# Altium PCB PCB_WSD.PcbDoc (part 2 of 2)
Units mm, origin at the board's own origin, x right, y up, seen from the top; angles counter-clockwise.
Board outline 55.63 x 89.28 mm, 2 copper layers (Top Layer, Bottom Layer); 49 components, 56 nets, 208 pads, 22 vias.
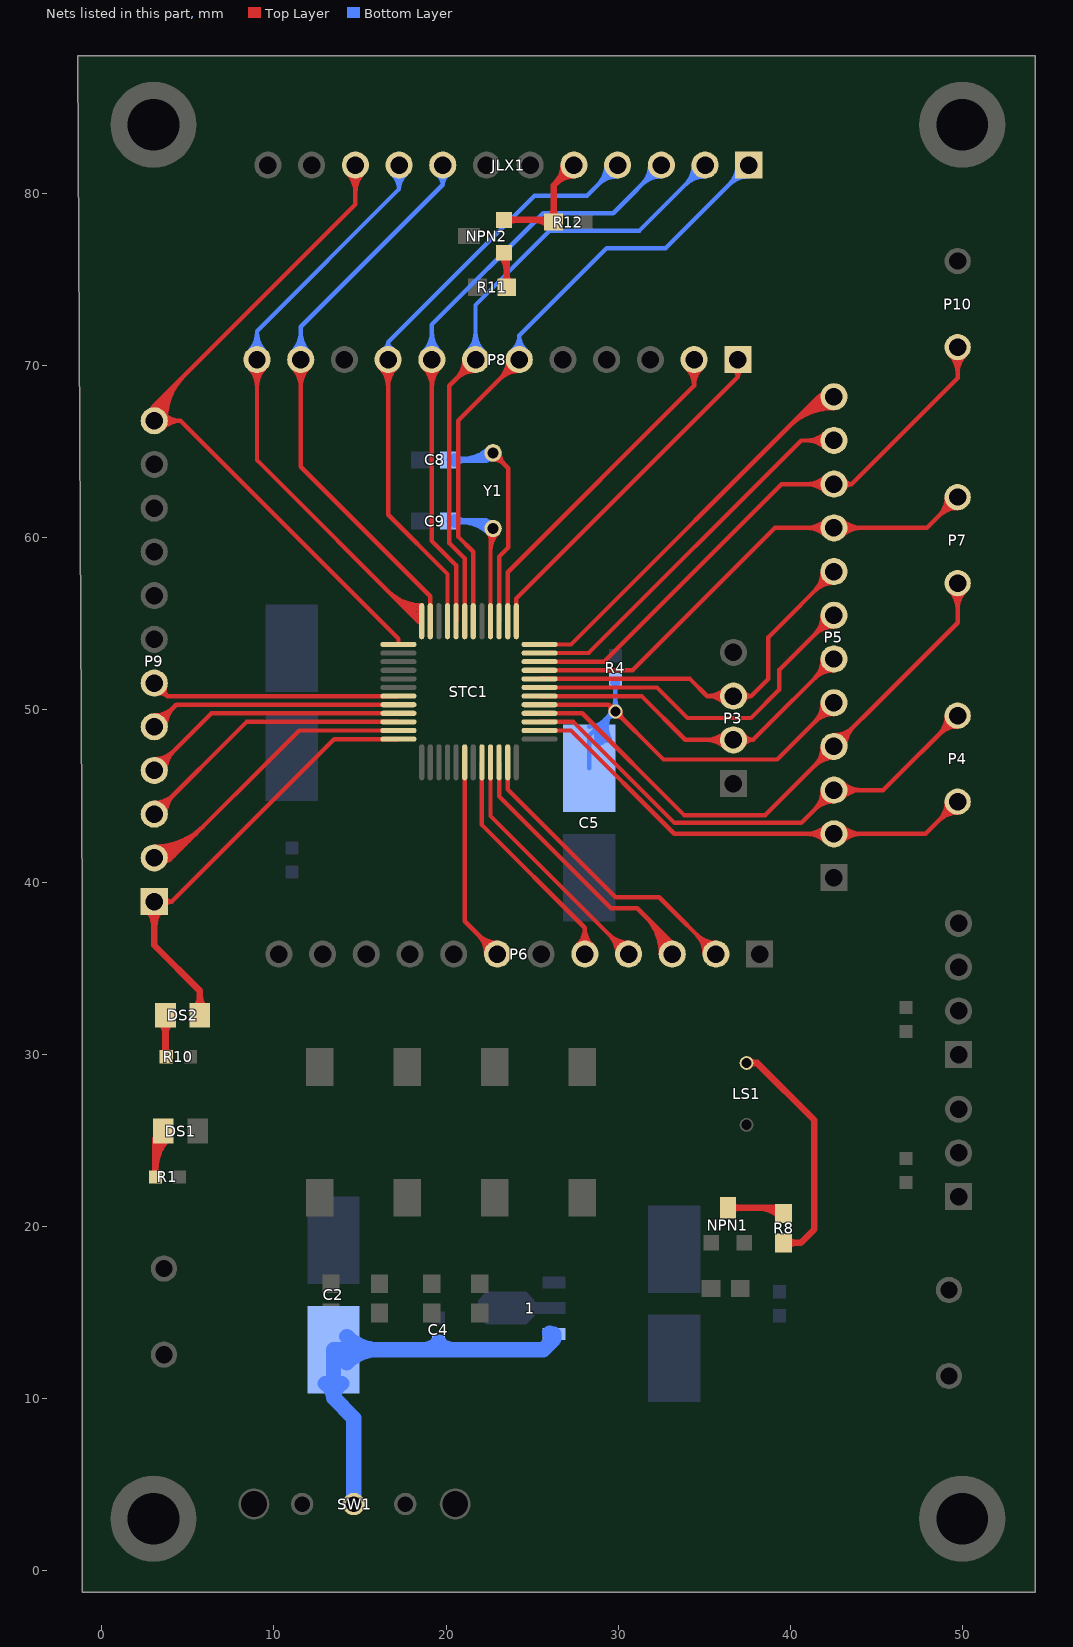
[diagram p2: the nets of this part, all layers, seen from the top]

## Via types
v1: diameter 1.2, hole 1, Top Layer to Bottom Layer, 21 vias
v2: diameter 0.8, hole 0.6, Top Layer to Bottom Layer, 1 vias

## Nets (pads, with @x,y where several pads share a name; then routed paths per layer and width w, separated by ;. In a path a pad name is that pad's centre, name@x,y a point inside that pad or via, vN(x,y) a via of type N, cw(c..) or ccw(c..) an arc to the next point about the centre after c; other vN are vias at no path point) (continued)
LCD-RS: JLX1.10 P9.12 STC1.25 | length 76.2
  Top Layer w0.254: JLX1.10@14.732,81.661 14.732,79.375 3.048,67.691 ; STC1.25@17.236,53.804 17.236,54.138 4.572,66.802 ; 3.048,67.691 cw(c2.78,67.691) 2.857,67.434 ccw(c2.78,67.691) 3.048,67.691 ; 3.048,67.691 ccw(c3.316,67.691) 3.239,67.434 cw(c3.316,67.691) 3.048,67.691 ; 3.048,67.691 P9.12@3.048,66.802 4.572,66.802 ; 3.986,66.802 cw(c3.986,67.681) 3.345,67.08 ccw(c3.986,67.681) 3.986,66.802 ; 3.986,66.802 ccw(c3.986,65.923) 3.345,66.524 cw(c3.986,65.923) 3.986,66.802 ; 4.572,66.802 cw(c4.572,68.23) 3.53,67.254 ccw(c4.572,68.23) 4.572,66.802 ; 4.572,66.802 ccw(c4.572,65.374) 3.53,66.35 cw(c4.572,65.374) 4.572,66.802 ; 14.732,80.067 cw(c16.326,80.067) 15.199,81.194 ccw(c16.326,80.067) 14.732,80.067 ; 14.732,80.067 ccw(c13.138,80.067) 14.265,81.194 cw(c13.138,80.067) 14.732,80.067 ; 14.732,80.68 cw(c15.713,80.68) 15.019,81.374 ccw(c15.713,80.68) 14.732,80.68 ; 14.732,80.68 ccw(c13.751,80.68) 14.445,81.374 cw(c13.751,80.68) 14.732,80.68 ; P9.12@2.692,66.802 cw(c3.98,66.802) 3.07,67.713 ccw(c3.98,66.802) P9.12@2.692,66.802 ; P9.12@2.946,66.802 cw(c4.847,66.802) 3.503,68.146 ccw(c4.847,66.802) P9.12@2.946,66.802 ; P9.12@3.2,66.802 cw(c5.715,66.802) 3.937,68.58 ccw(c5.715,66.802) P9.12@3.2,66.802 ; P9.12@3.454,66.802 cw(c6.582,66.802) 4.37,69.013 ccw(c6.582,66.802) P9.12@3.454,66.802 ; P9.12@3.708,66.802 cw(c7.449,66.802) 4.804,69.447 ccw(c7.449,66.802) P9.12@3.708,66.802
LCD-SCLK: JLX1.8 P8.11 STC1.23 | length 52
  Top Layer w0.254: P8.11@11.557,70.358 11.557,64.135 19.086,56.606 STC1.23@19.086,55.154 ; 11.557,68.764 cw(c13.151,68.764) 12.024,69.891 ccw(c13.151,68.764) 11.557,68.764 ; 11.557,68.764 ccw(c9.963,68.764) 11.09,69.891 cw(c9.963,68.764) 11.557,68.764 ; 11.557,69.377 cw(c12.538,69.377) 11.844,70.071 ccw(c12.538,69.377) 11.557,69.377 ; 11.557,69.377 ccw(c10.576,69.377) 11.27,70.071 cw(c10.576,69.377) 11.557,69.377
  Bottom Layer w0.254: P8.11@11.557,70.358 11.557,72.263 19.812,80.518 ; JLX1.8@19.812,81.661 19.812,80.518 ; 11.557,71.339 cw(c10.576,71.339) 11.27,70.645 ccw(c10.576,71.339) 11.557,71.339 ; 11.557,71.339 ccw(c12.538,71.339) 11.844,70.645 cw(c12.538,71.339) 11.557,71.339 ; 11.557,71.952 cw(c9.963,71.952) 11.09,70.825 ccw(c9.963,71.952) 11.557,71.952 ; 11.557,71.952 ccw(c13.151,71.952) 12.024,70.825 cw(c13.151,71.952) 11.557,71.952 ; 19.812,80.518 cw(c20.471,80.518) 20.142,81.089 ccw(c20.471,80.518) 19.812,80.518 ; 19.812,80.518 ccw(c19.153,80.518) 19.482,81.089 cw(c19.153,80.518) 19.812,80.518
LCD-SDA: JLX1.9 P8.12 STC1.24 | length 68.5
  Top Layer w0.254: P8.12@9.017,70.358 9.017,64.516 18.379,55.154 STC1.24@18.586,55.154 ; 9.017,68.764 cw(c10.611,68.764) 9.484,69.891 ccw(c10.611,68.764) 9.017,68.764 ; 9.017,68.764 ccw(c7.423,68.764) 8.55,69.891 cw(c7.423,68.764) 9.017,68.764 ; 9.017,69.377 cw(c9.998,69.377) 9.304,70.071 ccw(c9.998,69.377) 9.017,69.377 ; 9.017,69.377 ccw(c8.036,69.377) 8.73,70.071 cw(c8.036,69.377) 9.017,69.377 ; 16.657,56.876 ccw(c18.586,58.805) 18.586,56.077 cw(c18.586,58.805) 16.657,56.876 ; 17.091,56.442 ccw(c18.586,57.938) 18.586,55.823 cw(c18.586,57.938) 17.091,56.442 ; 17.524,56.009 ccw(c18.586,57.071) 18.586,55.569 cw(c18.586,57.071) 17.524,56.009 ; 17.958,55.575 ccw(c18.586,56.203) 18.586,55.315 cw(c18.586,56.203) 17.958,55.575 ; 18.391,55.142 ccw(c18.586,55.336) 18.586,55.061 cw(c18.586,55.336) 18.391,55.142
  Bottom Layer w0.254: P8.12@9.017,70.358 9.017,72.009 17.272,80.264 ; JLX1.9@17.272,81.661 17.272,80.264 ; 9.017,71.339 cw(c8.036,71.339) 8.73,70.645 ccw(c8.036,71.339) 9.017,71.339 ; 9.017,71.339 ccw(c9.998,71.339) 9.304,70.645 cw(c9.998,71.339) 9.017,71.339 ; 9.017,71.952 cw(c7.423,71.952) 8.55,70.825 ccw(c7.423,71.952) 9.017,71.952 ; 9.017,71.952 ccw(c10.611,71.952) 9.484,70.825 cw(c10.611,71.952) 9.017,71.952 ; 17.272,80.264 cw(c18.419,80.264) 17.691,81.151 ccw(c18.419,80.264) 17.272,80.264 ; 17.272,80.264 ccw(c16.125,80.264) 16.853,81.151 cw(c16.125,80.264) 17.272,80.264 ; 17.272,80.801 cw(c17.978,80.801) 17.53,81.347 ccw(c17.978,80.801) 17.272,80.801 ; 17.272,80.801 ccw(c16.566,80.801) 17.014,81.347 cw(c16.566,80.801) 17.272,80.801
LED: DS2.2 P9.1 STC1.36 | length 35.5
  Top Layer w0.254: P9.1@3.048,38.862 4.064,38.862 ; STC1.36@17.236,48.304 13.506,48.304 4.064,38.862 ; 4.064,38.862 cw(c4.064,39.313) 3.652,39.13 ccw(c4.064,39.313) 4.064,38.862 ; 4.064,38.862 ccw(c4.064,38.411) 3.652,38.594 cw(c4.064,38.411) 4.064,38.862
  Top Layer w0.381: P9.1@3.048,38.862 3.048,36.322 5.699,33.671 DS2.2@5.699,32.258 ; 3.048,37.421 cw(c4.489,37.421) 3.47,38.44 ccw(c4.489,37.421) 3.048,37.421 ; 3.048,37.421 ccw(c1.607,37.421) 2.626,38.44 cw(c1.607,37.421) 3.048,37.421 ; 5.699,33.372 cw(c4.71,33.372) 5.409,32.673 ccw(c4.71,33.372) 5.699,33.372 ; 5.699,33.372 ccw(c6.688,33.372) 5.989,32.673 cw(c6.688,33.372) 5.699,33.372
Net1_3: 1.3 C2.1 C4.2 SW1.2 | length 45.2
  Bottom Layer w0.889: SW1.2@14.636,3.854 14.636,8.859 13.462,10.033 ; 19.558,12.827 C4.2@19.558,13.271 ; 1.3@26.28,13.74 26.28,13.453 25.654,12.827 C2.1@13.462,12.827 13.462,10.033 ; C2.1@12.964,10.853 cw(c12.538,10.033) 13.462,10.033 ; C2.1@12.964,10.853 cw(c12.538,10.033) 13.462,10.033 ; C2.1@12.964,10.853 cw(c12.538,10.033) 13.462,10.033 ; C2.1@12.964,10.853 cw(c12.538,10.033) 13.462,10.033 ; 13.462,10.033 cw(c14.386,10.033) C2.1@13.96,10.853 ; 13.462,10.033 cw(c14.386,10.033) C2.1@13.96,10.853 ; 13.462,10.033 cw(c14.386,10.033) C2.1@13.96,10.853 ; 13.462,10.033 cw(c14.386,10.033) C2.1@13.96,10.853 ; 16.068,12.827 cw(c16.068,15.433) 14.225,13.59 ccw(c16.068,15.433) 16.068,12.827 ; 16.068,12.827 ccw(c16.068,10.221) 14.225,12.064 cw(c16.068,10.221) 16.068,12.827 ; 18.638,12.827 ccw(c18.638,14.191) 19.603,13.227 cw(c18.638,14.191) 18.638,12.827 ; C4.2@19.513,13.227 ccw(c20.478,14.191) 20.478,12.827 cw(c20.478,14.191) C4.2@19.513,13.227 ; 25.96,13.133 ccw(c25.585,13.508) 26.035,13.79 cw(c25.585,13.508) 25.96,13.133
NetC8_1: C8.1 STC1.15 Y1.1 | length 25.2
  Top Layer w0.254: Y1.1@22.733,64.938 23.622,64.049 23.622,59.436 23.086,58.9 STC1.15@23.086,55.154 ; 23.383,64.288 cw(c24.034,64.938) 23.114,64.938 ccw(c24.034,64.938) 23.383,64.288 ; 23.383,64.288 ccw(c22.733,63.637) 22.733,64.557 cw(c22.733,63.637) 23.383,64.288
  Bottom Layer w0.381: C8.1@20.209,64.527 22.322,64.527 ; Y1.1@22.733,64.938 22.322,64.527 ; 21.006,64.527 cw(c21.006,65.274) 20.478,64.746 ccw(c21.006,65.274) 21.006,64.527 ; 21.006,64.527 ccw(c21.006,63.78) 20.478,64.308 cw(c21.006,63.78) 21.006,64.527 ; 22.322,64.527 cw(c22.586,64.263) 22.665,64.628 ccw(c22.586,64.263) 22.322,64.527 ; 22.322,64.527 ccw(c22.058,64.791) 22.423,64.87 cw(c22.058,64.791) 22.322,64.527 ; 20.974,64.527 ccw(c20.974,66.697) 22.508,65.163 cw(c20.974,66.697) 20.974,64.527 ; 21.894,64.527 ccw(c21.894,65.777) 22.778,64.893 cw(c21.894,65.777) 21.894,64.527
NetC9_1: C9.1 STC1.16 Y1.2 | length 21.9
  Top Layer w0.254: STC1.16@22.586,55.154 22.586,60.391 Y1.2@22.733,60.538 ; Y1.2@22.464,60.269 cw(c22.168,59.973) 22.586,59.973 ccw(c22.168,59.973) Y1.2@22.464,60.269 ; 22.586,59.263 cw(c24.008,59.263) 23.002,60.269 ccw(c24.008,59.263) 22.586,59.263 ; 22.586,59.877 cw(c23.394,59.877) 22.823,60.448 ccw(c23.394,59.877) 22.586,59.877
  Bottom Layer w0.381: C9.1@20.209,60.971 22.3,60.971 ; Y1.2@22.733,60.538 22.3,60.971 ; 21.006,60.971 cw(c21.006,61.718) 20.478,61.19 ccw(c21.006,61.718) 21.006,60.971 ; 21.006,60.971 ccw(c21.006,60.224) 20.478,60.752 cw(c21.006,60.224) 21.006,60.971 ; 22.3,60.971 cw(c21.995,60.666) 22.42,60.592 ccw(c21.995,60.666) 22.3,60.971 ; 22.3,60.971 ccw(c22.605,61.276) 22.679,60.851 cw(c22.605,61.276) 22.3,60.971 ; 20.921,60.971 cw(c20.921,58.726) 22.508,60.313 ccw(c20.921,58.726) 20.921,60.971 ; 21.841,60.971 cw(c21.841,59.646) 22.778,60.583 ccw(c21.841,59.646) 21.841,60.971
NetDS1_1: DS1.1 R1.1 | length 10.9
  Top Layer w0.381: R1.1@3.111,22.86 3.111,25.066 DS1.1@3.572,25.527 ; 3.111,23.32 cw(c2.652,23.32) 2.977,22.995 ccw(c2.652,23.32) 3.111,23.32 ; 3.111,23.32 ccw(c3.571,23.32) 3.246,22.995 cw(c3.571,23.32) 3.111,23.32 ; 3.111,23.302 cw(c5.672,23.302) 3.862,25.112 ccw(c5.672,23.302) 3.111,23.302 ; 3.111,24.221 cw(c4.753,24.221) 3.592,25.382 ccw(c4.753,24.221) 3.111,24.221
NetDS2_1: DS2.1 R10.1 | length 6.5
  Top Layer w0.381: DS2.1@3.699,32.258 3.699,29.892 R10.1@3.746,29.845 ; 3.699,31.144 cw(c4.688,31.144) 3.989,31.843 ccw(c4.688,31.144) 3.699,31.144 ; 3.699,31.144 ccw(c2.71,31.144) 3.409,31.843 cw(c2.71,31.144) 3.699,31.144 ; 3.699,30.42 ccw(c4.321,30.42) 3.881,29.98 cw(c4.321,30.42) 3.699,30.42
NetJLX1_5: JLX1.5 NPN2.2 R12.2 | length 17.5
  Top Layer w0.381: NPN2.2@23.376,78.473 26.131,78.473 R12.2@26.256,78.348 26.256,80.485 JLX1.5@27.432,81.661 ; 24.02,78.473 cw(c24.02,79.117) 23.565,78.662 ccw(c24.02,79.117) 24.02,78.473 ; 24.02,78.473 ccw(c24.02,77.829) 23.565,78.284 cw(c24.02,77.829) 24.02,78.473 ; 26.256,79.095 cw(c25.509,79.095) 26.037,78.567 ccw(c25.509,79.095) 26.256,79.095 ; 26.256,79.095 ccw(c27.003,79.095) 26.475,78.567 cw(c27.003,79.095) 26.256,79.095 ; 26.413,80.642 cw(c27.432,79.623) 27.432,81.064 ccw(c27.432,79.623) 26.413,80.642 ; 26.413,80.642 ccw(c25.394,81.661) 26.835,81.661 cw(c25.394,81.661) 26.413,80.642 ; 25.157,78.473 cw(c25.157,77.299) 25.987,78.129 ccw(c25.157,77.299) 25.157,78.473
NetLS1_2: LS1.2 R8.1 | length 17.7
  Top Layer w0.381: LS1.2@37.465,29.486 38.078,29.486 41.402,26.162 41.402,19.812 40.624,19.034 R8.1@39.613,19.034 ; 37.971,29.486 cw(c37.971,29.992) 37.613,29.634 ccw(c37.971,29.992) 37.971,29.486 ; 37.971,29.486 ccw(c37.971,28.98) 37.613,29.338 cw(c37.971,28.98) 37.971,29.486 ; 40.36,19.034 cw(c40.36,19.781) 39.832,19.253 ccw(c40.36,19.781) 40.36,19.034 ; 40.36,19.034 ccw(c40.36,18.287) 39.832,18.815 cw(c40.36,18.287) 40.36,19.034
NetNPN1_3: NPN1.3 R8.2 | length 9.4
  Top Layer w0.381: NPN1.3@36.385,21.074 39.273,21.074 R8.2@39.613,20.734 ; 37.029,21.074 cw(c37.029,21.718) 36.574,21.263 ccw(c37.029,21.718) 37.029,21.074 ; 37.029,21.074 ccw(c37.029,20.43) 36.574,20.885 cw(c37.029,20.43) 37.029,21.074 ; 38.166,21.074 cw(c38.166,19.337) 39.394,20.565 ccw(c38.166,19.337) 38.166,21.074 ; 39.085,21.074 cw(c39.085,20.256) 39.664,20.835 ccw(c39.085,20.256) 39.085,21.074
NetNPN2_1: NPN2.1 R11.2 | length 6.2
  Top Layer w0.381: NPN2.1@23.376,76.568 23.528,76.416 R11.2@23.528,74.56 ; 23.528,75.307 cw(c22.781,75.307) 23.309,74.779 ccw(c22.781,75.307) 23.528,75.307 ; 23.528,75.307 ccw(c24.275,75.307) 23.747,74.779 cw(c24.275,75.307) 23.528,75.307 ; NPN2.1@23.187,76.379 cw(c22.365,75.557) 23.528,75.557 ccw(c22.365,75.557) NPN2.1@23.187,76.379
P4.0: JLX1.1 P8.6 STC1.18 | length 58.6
  Top Layer w0.254: STC1.18@21.586,55.154 21.586,59.186 20.701,60.071 20.701,66.802 P8.6@24.257,70.358 ; 23.13,69.231 cw(c24.257,68.103) 24.257,69.698 ccw(c24.257,68.103) 23.13,69.231 ; 23.13,69.231 ccw(c22.002,70.358) 23.597,70.358 cw(c22.002,70.358) 23.13,69.231 ; 23.563,69.664 cw(c24.257,68.97) 24.257,69.952 ccw(c24.257,68.97) 23.563,69.664 ; 23.563,69.664 ccw(c22.869,70.358) 23.851,70.358 cw(c22.869,70.358) 23.563,69.664
  Bottom Layer w0.254: P8.6@24.257,70.358 24.257,71.755 ; JLX1.1@37.592,81.661 32.766,76.835 29.337,76.835 24.257,71.755 ; 24.257,71.218 cw(c23.551,71.218) 23.999,70.672 ccw(c23.551,71.218) 24.257,71.218 ; 24.257,71.218 ccw(c24.963,71.218) 24.515,70.672 cw(c24.963,71.218) 24.257,71.218 ; 24.257,71.755 cw(c23.11,71.755) 23.838,70.868 ccw(c23.11,71.755) 24.257,71.755 ; 24.257,71.755 ccw(c25.404,71.755) 24.676,70.868 cw(c25.404,71.755) 24.257,71.755 ; 36.465,80.534 cw(c37.592,79.406) 37.592,81.001 ccw(c37.592,79.406) 36.465,80.534 ; 36.465,80.534 ccw(c35.337,81.661) 36.932,81.661 cw(c35.337,81.661) 36.465,80.534 ; JLX1.1@36.898,80.967 cw(c37.592,80.273) 37.592,81.255 ccw(c37.592,80.273) JLX1.1@36.898,80.967 ; JLX1.1@36.898,80.967 ccw(c36.204,81.661) 37.186,81.661 cw(c36.204,81.661) JLX1.1@36.898,80.967
P05: P9.2 STC1.35 | length 40.9
  Top Layer w0.254: P9.2@3.048,41.402 3.175,41.275 3.937,41.275 ; STC1.35@17.236,48.804 11.466,48.804 3.937,41.275 ; 3.937,41.275 cw(c3.937,41.51) 3.704,41.482 ccw(c3.937,41.51) 3.937,41.275 ; 3.937,41.275 ccw(c3.937,40.928) 3.631,41.091 cw(c3.937,40.928) 3.937,41.275 ; P9.2@3.048,41.046 ccw(c3.048,42.641) 4.175,41.513 cw(c3.048,42.641) P9.2@3.048,41.046 ; P9.2@3.048,41.3 ccw(c3.048,43.508) 4.609,41.947 cw(c3.048,43.508) P9.2@3.048,41.3 ; P9.2@3.048,41.554 ccw(c3.048,44.375) 5.043,42.381 cw(c3.048,44.375) P9.2@3.048,41.554 ; P9.2@3.048,41.808 ccw(c3.048,45.242) 5.476,42.814 cw(c3.048,45.242) P9.2@3.048,41.808 ; P9.2@3.048,42.062 ccw(c3.048,46.11) 5.91,43.248 cw(c3.048,46.11) P9.2@3.048,42.062
P06: P9.3 STC1.34 | length 24.5
  Top Layer w0.254: P9.3@3.048,43.942 8.41,49.304 STC1.34@17.236,49.304 ; 3.742,44.636 cw(c3.048,45.33) 3.048,44.348 ccw(c3.048,45.33) 3.742,44.636 ; 3.742,44.636 ccw(c4.436,43.942) 3.454,43.942 cw(c4.436,43.942) 3.742,44.636 ; 4.175,45.069 cw(c3.048,46.197) 3.048,44.602 ccw(c3.048,46.197) 4.175,45.069 ; 4.175,45.069 ccw(c5.303,43.942) 3.708,43.942 cw(c5.303,43.942) 4.175,45.069
P07: P9.4 STC1.33 | length 23.7
  Top Layer w0.254: P9.4@3.048,46.482 6.37,49.804 STC1.33@17.236,49.804 ; 3.742,47.176 cw(c3.048,47.87) 3.048,46.888 ccw(c3.048,47.87) 3.742,47.176 ; 3.742,47.176 ccw(c4.436,46.482) 3.454,46.482 cw(c4.436,46.482) 3.742,47.176 ; 4.175,47.609 cw(c3.048,48.737) 3.048,47.142 ccw(c3.048,48.737) 4.175,47.609 ; 4.175,47.609 ccw(c5.303,46.482) 3.708,46.482 cw(c5.303,46.482) 4.175,47.609
P11: P6.5 STC1.44 | length 21.2
  Top Layer w0.254: STC1.44@22.086,46.954 22.086,43.319 28.067,37.338 ; P6.5@28.067,35.814 28.067,37.338 ; 28.067,36.752 cw(c27.188,36.752) 27.789,36.111 ccw(c27.188,36.752) 28.067,36.752 ; 28.067,36.752 ccw(c28.946,36.752) 28.345,36.111 cw(c28.946,36.752) 28.067,36.752 ; 28.067,37.338 cw(c26.639,37.338) 27.615,36.296 ccw(c26.639,37.338) 28.067,37.338 ; 28.067,37.338 ccw(c29.495,37.338) 28.519,36.296 cw(c29.495,37.338) 28.067,37.338
P12: P6.4 STC1.45 | length 22.6
  Top Layer w0.254: STC1.45@22.586,46.954 22.586,43.835 P6.4@30.607,35.814 ; 29.48,36.941 cw(c28.352,35.814) 29.947,35.814 ccw(c28.352,35.814) 29.48,36.941 ; 29.48,36.941 ccw(c30.607,38.069) 30.607,36.474 cw(c30.607,38.069) 29.48,36.941 ; 29.913,36.508 cw(c29.219,35.814) 30.201,35.814 ccw(c29.219,35.814) 29.913,36.508 ; 29.913,36.508 ccw(c30.607,37.202) 30.607,36.22 cw(c30.607,37.202) 29.913,36.508
P13: P6.3 STC1.46 | length 30.1
  Top Layer w0.254: STC1.46@23.086,46.954 23.086,44.986 29.591,38.481 31.115,38.481 33.147,36.449 P6.3@33.147,35.814 ; 31.571,38.025 cw(c29.359,35.814) 32.487,35.814 ccw(c29.359,35.814) 31.571,38.025 ; 32.004,37.592 cw(c30.226,35.814) 32.741,35.814 ccw(c30.226,35.814) 32.004,37.592 ; 32.438,37.158 cw(c31.094,35.814) 32.995,35.814 ccw(c31.094,35.814) 32.438,37.158 ; 32.871,36.725 cw(c31.961,35.814) 33.249,35.814 ccw(c31.961,35.814) 32.871,36.725
P14: P6.2 STC1.47 | length 25.7
  Top Layer w0.254: STC1.47@23.586,46.954 23.586,45.375 29.845,39.116 32.385,39.116 P6.2@35.687,35.814 ; 34.56,36.941 cw(c33.432,35.814) 35.027,35.814 ccw(c33.432,35.814) 34.56,36.941 ; 34.56,36.941 ccw(c35.687,38.069) 35.687,36.474 cw(c35.687,38.069) 34.56,36.941 ; 34.993,36.508 cw(c34.299,35.814) 35.281,35.814 ccw(c34.299,35.814) 34.993,36.508 ; 34.993,36.508 ccw(c35.687,37.202) 35.687,36.22 cw(c35.687,37.202) 34.993,36.508
P15: P4.1 P5.2 STC1.2 | length 51.4
  Top Layer w0.254: STC1.2@25.436,48.804 27.262,48.804 33.267,42.799 47.867,42.799 P4.1@49.732,44.664 ; 40.951,42.799 cw(c40.951,41.205) 42.078,42.332 ccw(c40.951,41.205) 40.951,42.799 ; 40.951,42.799 ccw(c40.951,44.393) 42.078,43.266 cw(c40.951,44.393) 40.951,42.799 ; 41.564,42.799 cw(c41.564,41.818) 42.258,42.512 ccw(c41.564,41.818) 41.564,42.799 ; 41.564,42.799 ccw(c41.564,43.78) 42.258,43.086 cw(c41.564,43.78) 41.564,42.799 ; 43.526,42.799 cw(c43.526,43.78) 42.832,43.086 ccw(c43.526,43.78) 43.526,42.799 ; 43.526,42.799 ccw(c43.526,41.818) 42.832,42.512 cw(c43.526,41.818) 43.526,42.799 ; 44.139,42.799 cw(c44.139,44.393) 43.012,43.266 ccw(c44.139,44.393) 44.139,42.799 ; 44.139,42.799 ccw(c44.139,41.205) 43.012,42.332 cw(c44.139,41.205) 44.139,42.799 ; 48.648,43.58 cw(c49.732,42.496) 49.732,44.029 ccw(c49.732,42.496) 48.648,43.58 ; 48.648,43.58 ccw(c47.564,44.664) 49.097,44.664 cw(c47.564,44.664) 48.648,43.58 ; 49.082,44.014 cw(c49.732,43.363) 49.732,44.283 ccw(c49.732,43.363) 49.082,44.014 ; 49.082,44.014 ccw(c48.431,44.664) 49.351,44.664 cw(c48.431,44.664) 49.082,44.014
P16: P4.2 P5.3 STC1.3 | length 53.2
  Top Layer w0.254: STC1.3@25.436,49.304 27.404,49.304 33.274,43.434 40.64,43.434 P5.3@42.545,45.339 45.407,45.339 P4.2@49.732,49.664 ; 41.418,44.212 cw(c42.545,43.084) 42.545,44.679 ccw(c42.545,43.084) 41.418,44.212 ; 41.418,44.212 ccw(c40.29,45.339) 41.885,45.339 cw(c40.29,45.339) 41.418,44.212 ; 41.851,44.645 cw(c42.545,43.951) 42.545,44.933 ccw(c42.545,43.951) 41.851,44.645 ; 41.851,44.645 ccw(c41.157,45.339) 42.139,45.339 cw(c41.157,45.339) 41.851,44.645 ; 43.526,45.339 cw(c43.526,46.32) 42.832,45.626 ccw(c43.526,46.32) 43.526,45.339 ; 43.526,45.339 ccw(c43.526,44.358) 42.832,45.052 cw(c43.526,44.358) 43.526,45.339 ; 44.139,45.339 cw(c44.139,46.933) 43.012,45.806 ccw(c44.139,46.933) 44.139,45.339 ; 44.139,45.339 ccw(c44.139,43.745) 43.012,44.872 cw(c44.139,43.745) 44.139,45.339 ; 48.648,48.58 cw(c49.732,47.496) 49.732,49.029 ccw(c49.732,47.496) 48.648,48.58 ; 48.648,48.58 ccw(c47.564,49.664) 49.097,49.664 cw(c47.564,49.664) 48.648,48.58 ; 49.082,49.014 cw(c49.732,48.363) 49.732,49.283 ccw(c49.732,48.363) 49.082,49.014 ; 49.082,49.014 ccw(c48.431,49.664) 49.351,49.664 cw(c48.431,49.664) 49.082,49.014
P17: P5.4 P7.1 STC1.4 | length 57.6
  Top Layer w0.254: STC1.4@25.436,49.804 27.92,49.804 33.836,43.888 38.554,43.888 49.732,55.066 P7.1@49.732,57.364 ; 41.418,46.752 cw(c42.545,45.624) 42.545,47.219 ccw(c42.545,45.624) 41.418,46.752 ; 41.418,46.752 ccw(c40.29,47.879) 41.885,47.879 cw(c40.29,47.879) 41.418,46.752 ; 41.851,47.185 cw(c42.545,46.491) 42.545,47.473 ccw(c42.545,46.491) 41.851,47.185 ; 41.851,47.185 ccw(c41.157,47.879) 42.139,47.879 cw(c41.157,47.879) 41.851,47.185 ; 43.239,48.573 cw(c42.545,49.267) 42.545,48.285 ccw(c42.545,49.267) 43.239,48.573 ; 43.239,48.573 ccw(c43.933,47.879) 42.951,47.879 cw(c43.933,47.879) 43.239,48.573 ; 43.672,49.006 cw(c42.545,50.134) 42.545,48.539 ccw(c42.545,50.134) 43.672,49.006 ; 43.672,49.006 ccw(c44.8,47.879) 43.205,47.879 cw(c44.8,47.879) 43.672,49.006 ; 49.732,55.831 cw(c51.265,55.831) 50.181,56.915 ccw(c51.265,55.831) 49.732,55.831 ; 49.732,55.831 ccw(c48.199,55.831) 49.283,56.915 cw(c48.199,55.831) 49.732,55.831 ; 49.732,56.444 cw(c50.652,56.444) 50.001,57.095 ccw(c50.652,56.444) 49.732,56.444 ; 49.732,56.444 ccw(c48.812,56.444) 49.463,57.095 cw(c48.812,56.444) 49.732,56.444
P20: JLX1.2 P8.7 STC1.19 | length 60.4
  Top Layer w0.254: STC1.19@21.086,55.154 21.086,58.801 20.193,59.694 20.193,68.834 P8.7@21.717,70.358 ; 20.59,69.231 cw(c21.717,68.103) 21.717,69.698 ccw(c21.717,68.103) 20.59,69.231 ; 20.59,69.231 ccw(c19.462,70.358) 21.057,70.358 cw(c19.462,70.358) 20.59,69.231 ; 21.023,69.664 cw(c21.717,68.97) 21.717,69.952 ccw(c21.717,68.97) 21.023,69.664 ; 21.023,69.664 ccw(c20.329,70.358) 21.311,70.358 cw(c20.329,70.358) 21.023,69.664
  Bottom Layer w0.254: P8.7@21.717,70.358 21.717,73.533 26.035,77.851 31.242,77.851 JLX1.2@35.052,81.661 ; 21.717,71.339 cw(c20.736,71.339) 21.43,70.645 ccw(c20.736,71.339) 21.717,71.339 ; 21.717,71.339 ccw(c22.698,71.339) 22.004,70.645 cw(c22.698,71.339) 21.717,71.339 ; 21.717,71.952 cw(c20.123,71.952) 21.25,70.825 ccw(c20.123,71.952) 21.717,71.952 ; 21.717,71.952 ccw(c23.311,71.952) 22.184,70.825 cw(c23.311,71.952) 21.717,71.952 ; 33.925,80.534 cw(c35.052,79.406) 35.052,81.001 ccw(c35.052,79.406) 33.925,80.534 ; 33.925,80.534 ccw(c32.797,81.661) 34.392,81.661 cw(c32.797,81.661) 33.925,80.534 ; 34.358,80.967 cw(c35.052,80.273) 35.052,81.255 ccw(c35.052,80.273) 34.358,80.967 ; 34.358,80.967 ccw(c33.664,81.661) 34.646,81.661 cw(c33.664,81.661) 34.358,80.967
P21: JLX1.3 P8.8 STC1.20 | length 59.3
  Top Layer w0.254: P8.8@19.177,70.358 19.177,59.817 20.586,58.408 STC1.20@20.586,55.154 ; 19.177,68.764 cw(c20.771,68.764) 19.644,69.891 ccw(c20.771,68.764) 19.177,68.764 ; 19.177,68.764 ccw(c17.583,68.764) 18.71,69.891 cw(c17.583,68.764) 19.177,68.764 ; 19.177,69.377 cw(c20.158,69.377) 19.464,70.071 ccw(c20.158,69.377) 19.177,69.377 ; 19.177,69.377 ccw(c18.196,69.377) 18.89,70.071 cw(c18.196,69.377) 19.177,69.377
  Bottom Layer w0.254: P8.8@19.177,70.358 19.177,72.39 25.654,78.867 29.718,78.867 JLX1.3@32.512,81.661 ; 19.177,71.339 cw(c18.196,71.339) 18.89,70.645 ccw(c18.196,71.339) 19.177,71.339 ; 19.177,71.339 ccw(c20.158,71.339) 19.464,70.645 cw(c20.158,71.339) 19.177,71.339 ; 19.177,71.952 cw(c17.583,71.952) 18.71,70.825 ccw(c17.583,71.952) 19.177,71.952 ; 19.177,71.952 ccw(c20.771,71.952) 19.644,70.825 cw(c20.771,71.952) 19.177,71.952 ; 31.385,80.534 cw(c32.512,79.406) 32.512,81.001 ccw(c32.512,79.406) 31.385,80.534 ; 31.385,80.534 ccw(c30.257,81.661) 31.852,81.661 cw(c30.257,81.661) 31.385,80.534 ; 31.818,80.967 cw(c32.512,80.273) 32.512,81.255 ccw(c32.512,80.273) 31.818,80.967 ; 31.818,80.967 ccw(c31.124,81.661) 32.106,81.661 cw(c31.124,81.661) 31.818,80.967
P22: JLX1.4 P8.9 STC1.21 | length 53.5
  Top Layer w0.254: P8.9@16.637,70.358 16.637,61.341 20.086,57.892 STC1.21@20.086,55.154 ; 16.637,68.764 cw(c18.231,68.764) 17.104,69.891 ccw(c18.231,68.764) 16.637,68.764 ; 16.637,68.764 ccw(c15.043,68.764) 16.17,69.891 cw(c15.043,68.764) 16.637,68.764 ; 16.637,69.377 cw(c17.618,69.377) 16.924,70.071 ccw(c17.618,69.377) 16.637,69.377 ; 16.637,69.377 ccw(c15.656,69.377) 16.35,70.071 cw(c15.656,69.377) 16.637,69.377
  Bottom Layer w0.254: P8.9@16.637,70.358 16.637,71.374 ; JLX1.4@29.972,81.661 28.194,79.883 25.146,79.883 16.637,71.374 ; 16.637,71.374 cw(c16.186,71.374) 16.369,70.962 ccw(c16.186,71.374) 16.637,71.374 ; 16.637,71.374 ccw(c17.088,71.374) 16.905,70.962 cw(c17.088,71.374) 16.637,71.374 ; 28.845,80.534 cw(c29.972,79.406) 29.972,81.001 ccw(c29.972,79.406) 28.845,80.534 ; 28.845,80.534 ccw(c27.717,81.661) 29.312,81.661 cw(c27.717,81.661) 28.845,80.534 ; 29.278,80.967 cw(c29.972,80.273) 29.972,81.255 ccw(c29.972,80.273) 29.278,80.967 ; 29.278,80.967 ccw(c28.584,81.661) 29.566,81.661 cw(c28.584,81.661) 29.278,80.967
P30: P3.2 P5.6 STC1.6 | length 39.1
  Top Layer w0.254: STC1.6@25.436,50.804 31.365,50.804 33.909,48.26 37.846,48.26 ; P5.6@42.545,52.959 37.846,48.26 ; 35.109,48.26 cw(c35.109,46.666) 36.236,47.793 ccw(c35.109,46.666) 35.109,48.26 ; 35.109,48.26 ccw(c35.109,49.854) 36.236,48.727 cw(c35.109,49.854) 35.109,48.26 ; 35.722,48.26 cw(c35.722,47.279) 36.416,47.973 ccw(c35.722,47.279) 35.722,48.26 ; 35.722,48.26 ccw(c35.722,49.241) 36.416,48.547 cw(c35.722,49.241) 35.722,48.26 ; 37.846,48.26 cw(c37.846,48.919) 37.275,48.59 ccw(c37.846,48.919) 37.846,48.26 ; 37.846,48.26 ccw(c37.846,47.601) 37.275,47.93 cw(c37.846,47.601) 37.846,48.26 ; 41.418,51.832 cw(c42.545,50.704) 42.545,52.299 ccw(c42.545,50.704) 41.418,51.832 ; 41.418,51.832 ccw(c40.29,52.959) 41.885,52.959 cw(c40.29,52.959) 41.418,51.832 ; 41.851,52.265 cw(c42.545,51.571) 42.545,52.553 ccw(c42.545,51.571) 41.851,52.265 ; 41.851,52.265 ccw(c41.157,52.959) 42.139,52.959 cw(c41.157,52.959) 41.851,52.265
P31: P3.3 P5.8 STC1.8 | length 39.7
  Top Layer w0.254: STC1.8@25.436,51.804 34.175,51.804 35.179,50.8 ; P5.8@42.545,58.039 38.735,54.229 38.735,51.816 37.719,50.8 ; 35.179,50.8 cw(c35.179,49.372) 36.221,50.348 ccw(c35.179,49.372) 35.179,50.8 ; 35.179,50.8 ccw(c35.179,52.228) 36.221,51.252 cw(c35.179,52.228) 35.179,50.8 ; 35.179,50.8 37.719,50.8 ; 35.765,50.8 cw(c35.765,49.921) 36.406,50.522 ccw(c35.765,49.921) 35.765,50.8 ; 35.765,50.8 ccw(c35.765,51.679) 36.406,51.078 cw(c35.765,51.679) 35.765,50.8 ; 37.719,50.8 cw(c37.719,51.251) 37.307,51.068 ccw(c37.719,51.251) 37.719,50.8 ; 37.719,50.8 ccw(c37.719,50.349) 37.307,50.532 cw(c37.719,50.349) 37.719,50.8 ; 41.418,56.912 cw(c42.545,55.784) 42.545,57.379 ccw(c42.545,55.784) 41.418,56.912 ; 41.418,56.912 ccw(c40.29,58.039) 41.885,58.039 cw(c40.29,58.039) 41.418,56.912 ; 41.851,57.345 cw(c42.545,56.651) 42.545,57.633 ccw(c42.545,56.651) 41.851,57.345 ; 41.851,57.345 ccw(c41.157,58.039) 42.139,58.039 cw(c41.157,58.039) 41.851,57.345
P32: P5.9 P7.2 STC1.9 | length 52.4
  Top Layer w0.254: STC1.9@25.436,52.304 30.841,52.304 39.116,60.579 47.947,60.579 P7.2@49.732,62.364 ; 40.951,60.579 cw(c40.951,58.985) 42.078,60.112 ccw(c40.951,58.985) 40.951,60.579 ; 40.951,60.579 ccw(c40.951,62.173) 42.078,61.046 cw(c40.951,62.173) 40.951,60.579 ; 41.564,60.579 cw(c41.564,59.598) 42.258,60.292 ccw(c41.564,59.598) 41.564,60.579 ; 41.564,60.579 ccw(c41.564,61.56) 42.258,60.866 cw(c41.564,61.56) 41.564,60.579 ; 43.526,60.579 cw(c43.526,61.56) 42.832,60.866 ccw(c43.526,61.56) 43.526,60.579 ; 43.526,60.579 ccw(c43.526,59.598) 42.832,60.292 cw(c43.526,59.598) 43.526,60.579 ; 44.139,60.579 cw(c44.139,62.173) 43.012,61.046 ccw(c44.139,62.173) 44.139,60.579 ; 44.139,60.579 ccw(c44.139,58.985) 43.012,60.112 cw(c44.139,58.985) 44.139,60.579 ; 48.648,61.28 cw(c49.732,60.196) 49.732,61.729 ccw(c49.732,60.196) 48.648,61.28 ; 48.648,61.28 ccw(c47.564,62.364) 49.097,62.364 cw(c47.564,62.364) 48.648,61.28 ; 49.082,61.714 cw(c49.732,61.063) 49.732,61.983 ccw(c49.732,61.063) 49.082,61.714 ; 49.082,61.714 ccw(c48.431,62.364) 49.351,62.364 cw(c48.431,62.364) 49.082,61.714
P33: P5.10 P10.1 STC1.10 | length 50.8
  Top Layer w0.254: STC1.10@25.436,52.804 29.182,52.804 39.497,63.119 43.561,63.119 ; P10.1@49.732,71.08 49.732,69.29 43.561,63.119 ; 40.951,63.119 cw(c40.951,61.525) 42.078,62.652 ccw(c40.951,61.525) 40.951,63.119 ; 40.951,63.119 ccw(c40.951,64.713) 42.078,63.586 cw(c40.951,64.713) 40.951,63.119 ; 41.564,63.119 cw(c41.564,62.138) 42.258,62.832 ccw(c41.564,62.138) 41.564,63.119 ; 41.564,63.119 ccw(c41.564,64.1) 42.258,63.406 cw(c41.564,64.1) 41.564,63.119 ; 43.561,63.119 cw(c43.561,63.57) 43.149,63.387 ccw(c43.561,63.57) 43.561,63.119 ; 43.561,63.119 ccw(c43.561,62.668) 43.149,62.851 cw(c43.561,62.668) 43.561,63.119 ; 49.732,69.547 cw(c51.265,69.547) 50.181,70.631 ccw(c51.265,69.547) 49.732,69.547 ; 49.732,69.547 ccw(c48.199,69.547) 49.283,70.631 cw(c48.199,69.547) 49.732,69.547 ; 49.732,70.16 cw(c50.652,70.16) 50.001,70.811 ccw(c50.652,70.16) 49.732,70.16 ; 49.732,70.16 ccw(c48.812,70.16) 49.463,70.811 cw(c48.812,70.16) 49.732,70.16
P34: P5.11 STC1.11 | length 30.3
  Top Layer w0.254: STC1.11@25.436,53.304 28.285,53.304 40.64,65.659 P5.11@42.545,65.659 ; 40.951,65.659 cw(c40.951,64.065) 42.078,65.192 ccw(c40.951,64.065) 40.951,65.659 ; 40.951,65.659 ccw(c40.951,67.253) 42.078,66.126 cw(c40.951,67.253) 40.951,65.659 ; 41.564,65.659 cw(c41.564,64.678) 42.258,65.372 ccw(c41.564,64.678) 41.564,65.659 ; 41.564,65.659 ccw(c41.564,66.64) 42.258,65.946 cw(c41.564,66.64) 41.564,65.659
P35: P5.12 STC1.12 | length 44.2
  Top Layer w0.254: STC1.12@25.436,53.804 27.261,53.804 41.656,68.199 ; P5.12@42.545,68.199 41.656,68.199 ; 41.656,68.199 cw(c41.656,67.931) 41.913,68.008 ccw(c41.656,67.931) 41.656,68.199 ; 41.656,68.199 ccw(c41.656,68.467) 41.913,68.39 cw(c41.656,68.467) 41.656,68.199 ; 39.9,66.443 cw(c42.545,63.798) 42.545,67.539 ccw(c42.545,63.798) 39.9,66.443 ; 40.334,66.877 cw(c42.545,64.665) 42.545,67.793 ccw(c42.545,64.665) 40.334,66.877 ; 40.767,67.31 cw(c42.545,65.532) 42.545,68.047 ccw(c42.545,65.532) 40.767,67.31 ; 41.201,67.744 cw(c42.545,66.4) 42.545,68.301 ccw(c42.545,66.4) 41.201,67.744 ; 41.634,68.177 cw(c42.545,67.267) 42.545,68.555 ccw(c42.545,67.267) 41.634,68.177
P36: P8.1 STC1.13 | length 22.6
  Top Layer w0.254: STC1.13@24.086,55.154 24.086,56.471 36.957,69.342 ; P8.1@36.957,70.358 36.957,69.342 ; 36.957,69.342 cw(c37.408,69.342) 37.225,69.754 ccw(c37.408,69.342) 36.957,69.342 ; 36.957,69.342 ccw(c36.506,69.342) 36.689,69.754 cw(c36.506,69.342) 36.957,69.342
P37: P8.2 STC1.14 | length 27.2
  Top Layer w0.254: STC1.14@23.586,55.154 23.586,58.003 34.417,68.834 ; P8.2@34.417,70.358 34.417,68.834 ; 34.417,68.834 cw(c35.845,68.834) 34.869,69.876 ccw(c35.845,68.834) 34.417,68.834 ; 34.417,68.834 ccw(c32.989,68.834) 33.965,69.876 cw(c32.989,68.834) 34.417,68.834 ; 34.417,69.42 cw(c35.296,69.42) 34.695,70.061 ccw(c35.296,69.42) 34.417,69.42 ; 34.417,69.42 ccw(c33.538,69.42) 34.139,70.061 cw(c33.538,69.42) 34.417,69.42
P41: P9.6 STC1.31 | length 16.9
  Top Layer w0.254: P9.6@3.048,51.562 3.806,50.804 ; STC1.31@17.236,50.804 3.806,50.804 ; 3.806,50.804 cw(c4.188,51.186) 3.675,51.355 ccw(c4.188,51.186) 3.806,50.804 ; 3.806,50.804 ccw(c3.424,50.422) 3.255,50.935 cw(c3.424,50.422) 3.806,50.804
P42: P6.7 STC1.42 | length 20
  Top Layer w0.254: STC1.42@21.086,46.954 21.086,37.715 P6.7@22.987,35.814 ; 21.86,36.941 cw(c20.732,35.814) 22.327,35.814 ccw(c20.732,35.814) 21.86,36.941 ; 21.86,36.941 ccw(c22.987,38.069) 22.987,36.474 cw(c22.987,38.069) 21.86,36.941 ; 22.293,36.508 cw(c21.599,35.814) 22.581,35.814 ccw(c21.599,35.814) 22.293,36.508 ; 22.293,36.508 ccw(c22.987,37.202) 22.987,36.22 cw(c22.987,37.202) 22.293,36.508
P43: P5.7 STC1.7 | length 29.1
  Top Layer w0.254: STC1.7@25.436,51.304 32.262,51.304 34.036,49.53 37.719,49.53 39.37,51.181 39.37,52.324 P5.7@42.545,55.499 ; 41.418,54.372 cw(c42.545,53.244) 42.545,54.839 ccw(c42.545,53.244) 41.418,54.372 ; 41.418,54.372 ccw(c40.29,55.499) 41.885,55.499 cw(c40.29,55.499) 41.418,54.372 ; 41.851,54.805 cw(c42.545,54.111) 42.545,55.093 ccw(c42.545,54.111) 41.851,54.805 ; 41.851,54.805 ccw(c41.157,55.499) 42.139,55.499 cw(c41.157,55.499) 41.851,54.805
P46: P9.5 STC1.32 | length 22.8
  Top Layer w0.254: P9.5@3.048,49.022 4.33,50.304 STC1.32@17.236,50.304 ; 3.742,49.716 cw(c3.048,50.41) 3.048,49.428 ccw(c3.048,50.41) 3.742,49.716 ; 3.742,49.716 ccw(c4.436,49.022) 3.454,49.022 cw(c4.436,49.022) 3.742,49.716 ; 4.175,50.149 cw(c3.048,51.277) 3.048,49.682 ccw(c3.048,51.277) 4.175,50.149 ; 4.175,50.149 ccw(c5.303,49.022) 3.708,49.022 cw(c5.303,49.022) 4.175,50.149
P47: C5.2 P5.5 R4.2 STC1.5 | length 57.7
  Top Layer w0.254: STC1.5@25.436,50.304 29.452,50.304 ; P5.5@42.545,50.419 39.243,47.117 32.639,47.117 29.452,50.304 ; 29.452,50.304 cw(c29.149,50) 29.574,49.946 ccw(c29.149,50) 29.452,50.304 ; 29.452,50.304 ccw(c29.756,50.607) 29.81,50.182 cw(c29.756,50.607) 29.452,50.304 ; 30.311,49.445 cw(c30.777,49.911) 30.118,49.911 ccw(c30.777,49.911) 30.311,49.445 ; 30.311,49.445 ccw(c29.845,48.979) 29.845,49.638 cw(c29.845,48.979) 30.311,49.445 ; 41.418,49.292 cw(c42.545,48.164) 42.545,49.759 ccw(c42.545,48.164) 41.418,49.292 ; 41.418,49.292 ccw(c40.29,50.419) 41.885,50.419 cw(c40.29,50.419) 41.418,49.292 ; 41.851,49.725 cw(c42.545,49.031) 42.545,50.013 ccw(c42.545,49.031) 41.851,49.725 ; 41.851,49.725 ccw(c41.157,50.419) 42.139,50.419 cw(c41.157,50.419) 41.851,49.725
  Bottom Layer w0.254: C5.2@28.321,46.609 28.321,48.514 v2@29.718,49.911 ; R4.2@29.845,51.752 v2(29.845,49.911) v2@29.718,49.911 ; v2@29.718,49.911 ccw(c30.63,48.999) 29.522,48.339 cw(c30.63,48.999) v2@29.718,49.911 ; 29.845,50.57 cw(c29.186,50.57) 29.652,50.104 ccw(c29.186,50.57) 29.845,50.57 ; 29.845,50.57 ccw(c30.504,50.57) 30.038,50.104 cw(c30.504,50.57) 29.845,50.57 ; 29.845,51.139 cw(c30.458,51.139) 30.025,51.573 ccw(c30.458,51.139) 29.845,51.139 ; 29.845,51.139 ccw(c29.232,51.139) 29.665,51.573 cw(c29.232,51.139) 29.845,51.139 ; C5.2@28.321,49.022 ccw(c28.321,50.248) 29.188,49.381 cw(c28.321,50.248) C5.2@28.321,49.022 ; C5.2@28.867,47.95 cw(c29.761,48.482) 29.025,49.218 ccw(c29.761,48.482) C5.2@28.867,47.95 ; C5.2@29.085,48.08 cw(c30.051,48.654) 29.256,49.449 ccw(c30.051,48.654) C5.2@29.085,48.08 ; 29.162,49.355 cw(c29.845,48.672) 29.845,49.638 ccw(c29.845,48.672) 29.162,49.355 ; C5.2@29.303,48.209 cw(c30.34,48.827) 29.487,49.68 ccw(c30.34,48.827) C5.2@29.303,48.209 ; 29.469,49.662 ccw(c29.22,49.911) 29.572,49.911 cw(c29.22,49.911) 29.469,49.662
pads on no net: DHT1.3 SW1.0 SW1.3

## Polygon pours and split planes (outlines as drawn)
GND on Top Layer (hatched 90Degree grid 0.254 track 0.254, remove dead copper): 52.705,0.381 0.127,0.381 0.127,86.614 52.578,86.614
GND on Bottom Layer (hatched 90Degree grid 0.254 track 0.254, remove dead copper): 52.578,0.381 0.127,0.381 0.127,86.614 52.578,86.614

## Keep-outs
Keep-Out Layer:
  lines w0.3: 0,0 0,87 53,87 53,0 0,0

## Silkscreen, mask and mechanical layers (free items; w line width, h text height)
Top Overlay:
  text "GND" at 40.767,80.391 h0.89
  text "P33" at 40.767,79.121 h0.89
  text "P32" at 40.767,77.851 h0.89
  text "P17" at 40.894,76.581 h0.89
  text "P16" at 40.894,75.311 h0.89
  text "P15" at 40.894,74.041 h0.89
  text "---->" at 41.021,73.279 h0.89
  text "P40" at 22.987,72.009 h0.89
  text "P20" at 20.066,71.882 h0.89
  text "P50" at 8.382,68.834 h0.89 r270
  text "P24" at 10.922,68.834 h0.89 r270
  text "P23" at 13.335,68.834 h0.89 r270
  text "P22" at 16.129,68.834 h0.89 r270
  text "P21" at 18.415,68.707 h0.89 r270
  text "VCC" at 28.829,68.707 h0.89 r270
  text "VCC" at 31.369,68.707 h0.89 r270
  text "P37" at 33.909,68.707 h0.89 r270
  text "P36" at 36.449,68.707 h0.89 r270
  text "GND" at 26.416,68.58 h0.89 r270
  text "P35" at 40.894,68.453 h0.89 r180
  text "P51" at 6.858,67.437 h0.89 r180
  text "P34" at 41.021,65.913 h0.89 r180
  text "P25" at 6.858,64.77 h0.89 r180
  text "P33" at 40.894,63.5 h0.89 r180
  text "P26" at 7.112,61.976 h0.89 r180
  text "P32" at 41.021,61.087 h0.89 r180
  text "P27" at 6.985,59.817 h0.89 r180
  text "P31" at 40.767,58.42 h0.89 r180
  text "P44" at 6.985,57.277 h0.89 r180
  text "P43" at 40.767,56.007 h0.89 r180
  text "P45" at 6.985,54.61 h0.89 r180
  text "P30" at 40.767,53.467 h0.89 r180
  text "GND" at 32.385,52.959 h0.89
  text "P41" at 6.985,52.07 h0.89 r180
  text "P47" at 40.767,50.673 h0.89 r180
  text "TXD" at 32.385,50.292 h0.89
  text "P46" at 7.112,49.53 h0.89 r180
  text "P17" at 40.894,48.133 h0.89 r180
  text "RXD" at 32.385,47.879 h0.89
  text "P07" at 7.112,46.863 h0.89 r180
  text "P16" at 40.894,45.593 h0.89 r180
  text "VCC" at 32.385,45.339 h0.89
  text "P06" at 6.985,44.45 h0.89 r180
  text "P15" at 40.767,43.18 h0.89 r180
  text "P05" at 7.112,41.91 h0.89 r180
  text "P53" at 40.894,41.402 h0.89 r180
  text "P52" at 37.465,40.132 h0.89 r270
  text "P00" at 17.272,39.878 h0.89 r270
  text "VCC" at 19.939,39.878 h0.89 r270
  text "P12" at 30.226,39.878 h0.89 r270
  text "P13" at 32.766,39.878 h0.89 r270
  text "P14" at 35.306,39.878 h0.89 r270
  text "P03" at 9.652,39.751 h0.89 r270
  text "P02" at 12.319,39.751 h0.89 r270
  text "P42" at 22.479,39.751 h0.89 r270
  text "P10" at 25.019,39.751 h0.89 r270
  text "P11" at 27.94,39.751 h0.89 r270
  text "P04" at 7.112,39.624 h0.89 r180
  text "P01" at 14.986,39.497 h0.89 r270
  text "8v" at 0.889,22.733 h0.89 r270
  text "5v" at 43.688,15.875 h0.89 r90
  text "-" at 43.561,10.922 h0.89 r90
  text "-" at 1.143,8.382 h0.89 r270
  text "OFF" at 17.78,7.493 h0.89
  text "ON" at 9.335,7.366 h0.89
  text "2013-12 by WS" at 40.767,6.731 h0.89
  text "Ver 1.0" at 40.767,4.826 h0.89
Drill Drawing:
  text ".LEGEND" at 106.41,-4.064 h0.89
  text "Drill Drawing." at 106.41,-6.604 h0.89

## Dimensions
0,0 to 0,87 on Mechanical 1
0,0 to 53,0 on Mechanical 1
